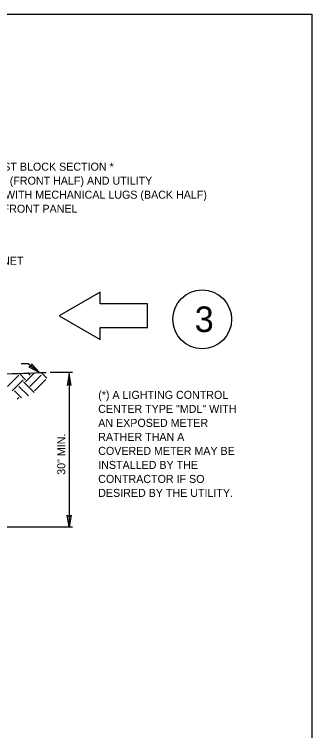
# Model space of a CAD drawing. Extents: x 99992 to 113392, y 99794 to 102182.
# Drawn here: x 102745 to 103192, y 101011 to 102085 of the extents above; entities that cross this region are included whole.
import ezdxf

# ---------------------------------------------------------------- set-up
doc = ezdxf.new("R2010")
doc.units = 0
for name, color, linetype in [('Border Organizer Shape', 7, 'Continuous'), ('Default', 7, 'Continuous'), ('QM Aggregate Gravel', 7, 'Continuous')]:
    doc.layers.add(name, color=color, linetype=linetype)

msp = doc.modelspace()

# ---------------------------------------------------------------- linework, layer by layer
at = {"layer": 'Border Organizer Shape'}
for p, q in [((102755.7, 101561.6), (102766, 101561.6)), ((102766, 101561.6), (102783.3, 101548.2)), ((102735.3, 101527.4), (102752.2, 101544.3)), ((102752.6, 101547.3), (102762.3, 101537.5)), ((102762.2, 101534.3), (102775.9, 101548)), ((102765.7, 101547.7), (102769.1, 101544.3)), ((102768.9, 101527.5), (102785.8, 101544.4)), ((102785.6, 101548.3), (102794.1, 101539.8)), ((102832.9, 101548.3), (102799.3, 101548.3)), ((102827.9, 101546.8), (102827.9, 101316.4)), ((102742, 101520.6), (102758.9, 101537.5)), ((102759.1, 101534.3), (102775.3, 101518.1)), ((102775.7, 101520.8), (102792.6, 101537.7)), ((102745.5, 101520.8), (102756.2, 101510.1)), ((102752.3, 101527.5), (102766.7, 101513.2)), ((102749.5, 101508.1), (102752, 101510.6)), ((102832.9, 101316.4), (102610.9, 101316.4))]:
    msp.add_line(p, q, dxfattribs=at)
for points in [[(102767.3, 101556.7), (102783.3, 101548.2), (102771, 101561.5), (102771.4, 101557.4)], [(102831, 101528.9), (102827.9, 101546.7), (102825, 101528.9), (102828, 101531.7)], [(102831, 101334.2), (102827.9, 101316.4), (102825, 101334.3), (102828, 101331.4)]]:
    msp.add_lwpolyline(points, close=True, dxfattribs=at)
msp.add_spline([(102511.3, 101547.3), (102546.7, 101548.5), (102560.6, 101548.7), (102574.5, 101548.3), (102602.4, 101546.5), (102630.2, 101544.7), (102644.1, 101544.3), (102658, 101544.4), (102793.3, 101548.5)], degree=3, dxfattribs=at)
at = {"layer": 'Default'}
msp.add_lwpolyline([(99992.2, 102085.3), (103191.9, 102085.3), (103191.9, 99885.7), (99992.2, 99885.7)], close=True, dxfattribs=at)
at = {"layer": 'QM Aggregate Gravel'}
msp.add_lwpolyline([(102813, 101633.3), (102874.5, 101597.9), (102874.5, 101615.6), (102945.4, 101615.6), (102945.4, 101651.1), (102874.5, 101651.1), (102874.5, 101668.8)], close=True, dxfattribs=at)
msp.add_circle((103027.5, 101628.1), 44.2, dxfattribs=at)

# ---------------------------------------------------------------- texts
at = {"layer": 'Border Organizer Shape'}
for s, p in [('1. UTILITY METER AND TEST BLOCK SECTION *', (102527.3, 101850.9)), ('2. DISTRIBUTION SECTION (FRONT HALF) AND UTILITY', (102527.3, 101829.9)), ('   TERMINATION SECTION WITH MECHANICAL LUGS (BACK HALF) ', (102527.3, 101808.9)), ('   SEPERATED BY A DEADFRONT PANEL', (102527.3, 101787.9)), (' PEDESTAL CABINET', (102596.9, 101709.9)), ('(*) A LIGHTING CONTROL ', (102871.4, 101508.8)), ('CENTER TYPE "MDL" WITH ', (102871.4, 101487.8)), ('AN EXPOSED METER ', (102871.4, 101466.8)), ('RATHER THAN A ', (102871.4, 101445.8)), ('COVERED METER MAY BE ', (102871.4, 101424.8)), ('INSTALLED BY THE ', (102871.4, 101403.8)), ('CONTRACTOR IF SO ', (102871.4, 101382.8)), ('DESIRED BY THE UTILITY.', (102871.4, 101361.8))]:
    msp.add_text(s, height=12, dxfattribs=at).set_placement(p)
msp.add_text('30" MIN.', height=12, rotation=90, dxfattribs=at).set_placement((102821.9, 101394.9))
at = {"layer": 'QM Aggregate Gravel'}
msp.add_text('3', height=38.3, dxfattribs=at).set_placement((103016.3, 101609))

doc.saveas('drawing.dxf')
